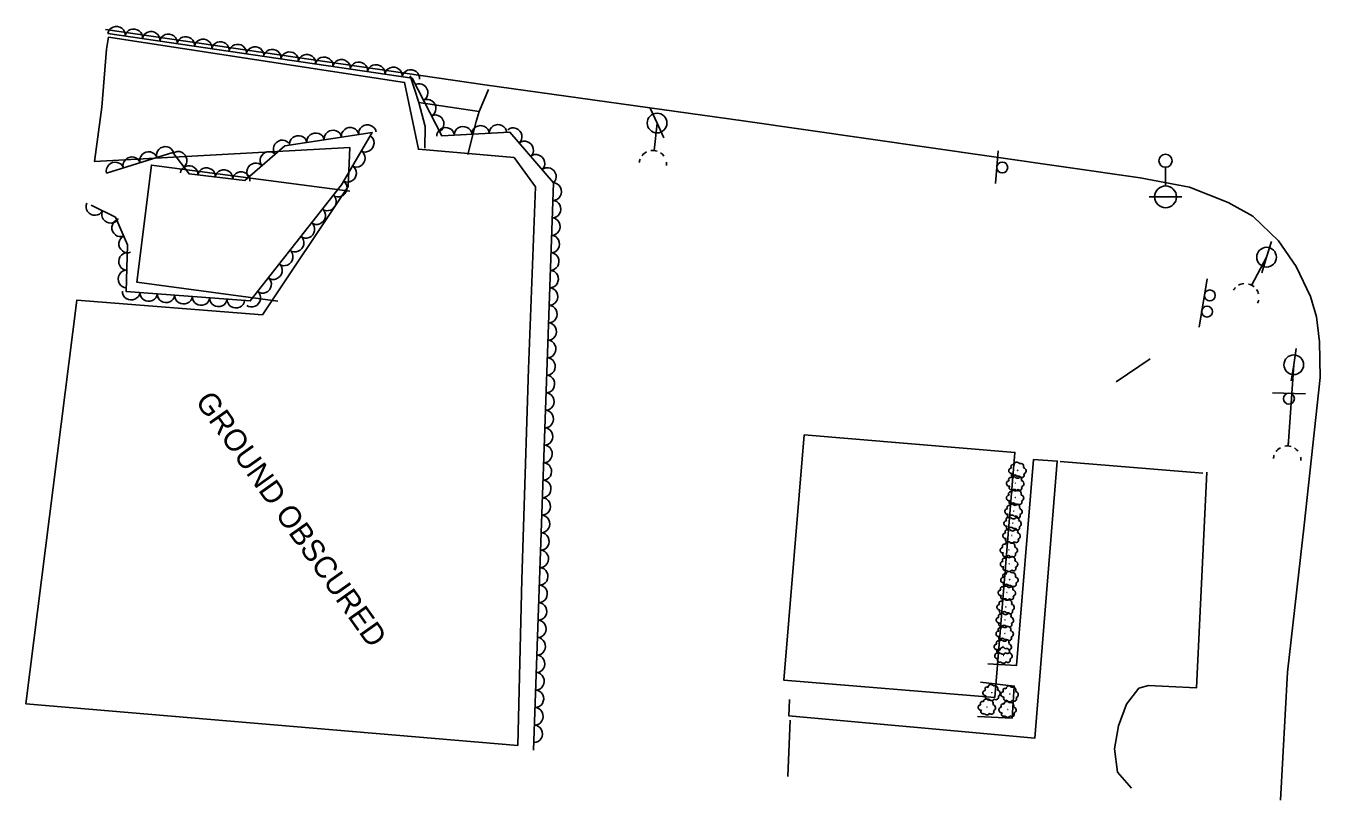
# Model space of a CAD drawing. Extents: x 1746719 to 1766531, y 631721 to 662391.
# Drawn here: x 1763206.3 to 1763502.1, y 632602.3 to 632779.3 of the extents above; entities that cross this region are included whole.
import ezdxf

# ---------------------------------------------------------------- set-up
doc = ezdxf.new("R2010")
doc.units = 0
for name, color, linetype in [('SURVEY - AERIAL SURVEY - Photo Control - Points - Elevations', 7, 'Continuous'), ('SURVEY - AERIAL SURVEY - Photo Control - Points - Locators', 7, 'Continuous'), ('SURVEY - AERIAL SURVEY - Photo Control with Text', 7, 'Continuous'), ('SURVEY - CENTERLINE - Existing Roads - Development', 7, 'Continuous'), ('SURVEY - CENTERLINE - Existing Roads Curve Text', 7, 'Continuous'), ('SURVEY - CONTROL - Grid', 7, 'Continuous')]:
    doc.layers.add(name, color=color, linetype=linetype)

msp = doc.modelspace()

# ---------------------------------------------------------------- linework, layer by layer
at = {"layer": 'SURVEY - AERIAL SURVEY - Photo Control - Points - Elevations'}
for points in [[(1763493.12, 632602.33), (1763494.69, 632631.56), (1763498.49, 632665.21), (1763502.14, 632698.92), (1763501.96, 632707.07), (1763501.3, 632712.82), (1763499.95, 632717.42), (1763496.65, 632724.29), (1763492.64, 632730.17), (1763486.79, 632735.8), (1763481.09, 632738.95), (1763472.31, 632742.44), (1763461, 632744.54), (1763427.02, 632749.42), (1763370.25, 632757.58), (1763311.24, 632765.81), (1763224.55, 632778.43)], [(1763312.07, 632764.79), (1763309.9, 632759.7), (1763296.17, 632761.8), (1763294.2, 632767.91)], [(1763296.17, 632761.8), (1763297.59, 632756.31), (1763297.55, 632751.35)], [(1763307.37, 632749.91), (1763309.25, 632757.41), (1763309.9, 632759.7)], [(1763442.71, 632679.75), (1763475.31, 632677.09)], [(1763459.02, 632605.06), (1763455.81, 632608.71), (1763455.17, 632614.02), (1763456.06, 632619.29), (1763457.86, 632624.3), (1763460.74, 632627.91), (1763462.91, 632628.56), (1763467.57, 632628.29), (1763473.86, 632627.99), (1763476.23, 632677.3)], [(1763381.03, 632620.62), (1763380.48, 632607.72)]]:
    msp.add_lwpolyline(points, dxfattribs=at)
at = {"layer": 'SURVEY - AERIAL SURVEY - Photo Control - Points - Locators'}
msp.add_lwpolyline([(1763225.25, 632776.7), (1763292.89, 632766.36), (1763296.04, 632751.11), (1763317.9, 632749.23), (1763322.81, 632742.51), (1763321.24, 632700.92), (1763319.65, 632652.79), (1763318.76, 632614.83), (1763206.34, 632624.37), (1763217.98, 632716.59), (1763260.38, 632713.26), (1763280.02, 632742.58), (1763280.4, 632751.46), (1763221.99, 632748.32), (1763223.73, 632760.75), (1763224.77, 632773.97), (1763225.25, 632776.7)], dxfattribs=at)
at = {"layer": 'SURVEY - AERIAL SURVEY - Photo Control with Text'}
for points in [[(1763225.06, 632777.56), (1763294.65, 632767.33), (1763301.44, 632754.13), (1763316.96, 632754.99), (1763326.91, 632743.43), (1763322.38, 632613.72)], [(1763224.79, 632745.66), (1763239.92, 632750.35), (1763243.63, 632745.45), (1763256.41, 632743.95), (1763265.52, 632751.84), (1763285.46, 632754.96), (1763278.44, 632742.94), (1763257.61, 632716.44), (1763229.22, 632718.62), (1763229.56, 632729.22), (1763226.79, 632735.58), (1763221.23, 632738.31)]]:
    msp.add_lwpolyline(points, dxfattribs=at)
for centre in [(1763433.02, 632677.71), (1763432.5, 632674.79), (1763432.47, 632671.48), (1763432.12, 632668.38), (1763431.91, 632665.63), (1763431.67, 632662.83), (1763431.04, 632659.53), (1763431.09, 632656.35), (1763431.18, 632652.73), (1763430.59, 632649.8), (1763430.3, 632646.49), (1763430.15, 632643.55), (1763430.1, 632640.42), (1763429.68, 632637.45), (1763429.81, 632635.39), (1763427.11, 632626.89), (1763431.23, 632626.58), (1763426.03, 632623.58), (1763430.75, 632623.03)]:
    msp.add_circle(centre, 0.022, dxfattribs=at)
for centre, radius, start, end in [((1763431.61, 632677.63), 0.629, 89.3771, 282.7968), ((1763431.91, 632678.58), 0.433, 49.3564, 228.1021), ((1763432.07, 632676.66), 0.479, 131.9958, 309.3149), ((1763432.82, 632678.95), 0.631, 27.2403, 184.0292), ((1763433.67, 632678.59), 0.719, 336.293, 113.8172), ((1763434.24, 632677.59), 0.714, 287.1888, 83.0273), ((1763431.09, 632674.71), 0.629, 89.3771, 282.7968), ((1763431.38, 632675.66), 0.433, 49.3564, 228.1021), ((1763431.55, 632673.74), 0.479, 131.9958, 309.3149), ((1763432.3, 632676.03), 0.631, 27.2403, 184.0292), ((1763432.98, 632676.6), 0.679, 207.2828, 334.1285), ((1763433.15, 632675.67), 0.719, 336.293, 113.8172), ((1763433.48, 632673.7), 0.527, 217.4417, 32.442), ((1763434.01, 632676.62), 0.527, 217.4417, 32.442), ((1763433.72, 632674.67), 0.714, 287.1888, 83.0273), ((1763431.06, 632671.4), 0.629, 89.3771, 282.7968), ((1763431.36, 632672.35), 0.433, 49.3564, 228.1021), ((1763432.27, 632672.72), 0.631, 27.2403, 184.0292), ((1763432.46, 632673.68), 0.679, 207.2828, 334.1285), ((1763433.12, 632672.35), 0.719, 336.293, 113.8172), ((1763433.69, 632671.36), 0.714, 287.1888, 83.0273), ((1763430.7, 632668.3), 0.629, 89.3771, 282.7968), ((1763431, 632669.25), 0.433, 49.3564, 228.1021), ((1763431.52, 632670.43), 0.479, 131.9958, 309.3149), ((1763431.91, 632669.63), 0.631, 27.2403, 184.0292), ((1763432.43, 632670.37), 0.679, 207.2828, 334.1285), ((1763432.76, 632669.26), 0.719, 336.293, 113.8172), ((1763433.46, 632670.39), 0.527, 217.4417, 32.442), ((1763433.33, 632668.26), 0.714, 287.1888, 83.0273), ((1763430.49, 632665.55), 0.629, 89.3771, 282.7968), ((1763430.79, 632666.5), 0.433, 49.3564, 228.1021), ((1763431.16, 632667.33), 0.479, 131.9958, 309.3149), ((1763431.7, 632666.87), 0.631, 27.2403, 184.0292), ((1763432.07, 632667.27), 0.679, 207.2828, 334.1285), ((1763432.55, 632666.51), 0.719, 336.293, 113.8172), ((1763433.1, 632667.3), 0.527, 217.4417, 32.442), ((1763433.12, 632665.51), 0.714, 287.1888, 83.0273), ((1763430.26, 632662.75), 0.629, 89.3771, 282.7968), ((1763430.55, 632663.7), 0.433, 49.3564, 228.1021), ((1763430.95, 632664.58), 0.479, 131.9958, 309.3149), ((1763431.46, 632664.07), 0.631, 27.2403, 184.0292), ((1763431.86, 632664.52), 0.679, 207.2828, 334.1285), ((1763432.31, 632663.71), 0.719, 336.293, 113.8172), ((1763432.89, 632664.54), 0.527, 217.4417, 32.442), ((1763432.89, 632662.71), 0.714, 287.1888, 83.0273), ((1763429.63, 632659.45), 0.629, 89.3771, 282.7968), ((1763429.92, 632660.4), 0.433, 49.3564, 228.1021), ((1763430.83, 632660.77), 0.631, 27.2403, 184.0292), ((1763430.72, 632661.78), 0.479, 131.9958, 309.3149), ((1763431.62, 632661.72), 0.679, 207.2828, 334.1285), ((1763431.68, 632660.41), 0.719, 336.293, 113.8172), ((1763432.65, 632661.74), 0.527, 217.4417, 32.442), ((1763432.25, 632659.41), 0.714, 287.1888, 83.0273), ((1763429.68, 632656.27), 0.629, 89.3771, 282.7968), ((1763429.97, 632657.22), 0.433, 49.3564, 228.1021), ((1763430.09, 632658.48), 0.479, 131.9958, 309.3149), ((1763430.89, 632657.59), 0.631, 27.2403, 184.0292), ((1763430.99, 632658.42), 0.679, 207.2828, 334.1285), ((1763431.74, 632657.23), 0.719, 336.293, 113.8172), ((1763432.02, 632658.44), 0.527, 217.4417, 32.442), ((1763432.31, 632656.23), 0.714, 287.1888, 83.0273), ((1763429.77, 632652.65), 0.629, 89.3771, 282.7968), ((1763430.06, 632653.6), 0.433, 49.3564, 228.1021), ((1763430.14, 632655.3), 0.479, 131.9958, 309.3149), ((1763430.97, 632653.98), 0.631, 27.2403, 184.0292), ((1763431.05, 632655.24), 0.679, 207.2828, 334.1285), ((1763431.82, 632653.61), 0.719, 336.293, 113.8172), ((1763432.07, 632655.26), 0.527, 217.4417, 32.442), ((1763432.4, 632652.61), 0.714, 287.1888, 83.0273), ((1763429.18, 632649.72), 0.629, 89.3771, 282.7968), ((1763429.47, 632650.67), 0.433, 49.3564, 228.1021), ((1763430.23, 632651.68), 0.479, 131.9958, 309.3149), ((1763430.38, 632651.04), 0.631, 27.2403, 184.0292), ((1763431.13, 632651.62), 0.679, 207.2828, 334.1285), ((1763431.23, 632650.68), 0.719, 336.293, 113.8172), ((1763432.16, 632651.65), 0.527, 217.4417, 32.442), ((1763431.81, 632649.68), 0.714, 287.1888, 83.0273), ((1763429.19, 632647.36), 0.433, 49.3564, 228.1021), ((1763429.64, 632648.75), 0.479, 131.9958, 309.3149), ((1763430.1, 632647.74), 0.631, 27.2403, 184.0292), ((1763430.54, 632648.69), 0.679, 207.2828, 334.1285), ((1763430.95, 632647.37), 0.719, 336.293, 113.8172), ((1763431.57, 632648.71), 0.527, 217.4417, 32.442), ((1763428.89, 632646.41), 0.629, 89.3771, 282.7968), ((1763429.03, 632644.42), 0.433, 49.3564, 228.1021), ((1763429.35, 632645.44), 0.479, 131.9958, 309.3149), ((1763429.94, 632644.79), 0.631, 27.2403, 184.0292), ((1763430.26, 632645.38), 0.679, 207.2828, 334.1285), ((1763430.79, 632644.43), 0.719, 336.293, 113.8172), ((1763431.28, 632645.41), 0.527, 217.4417, 32.442), ((1763431.52, 632646.37), 0.714, 287.1888, 83.0273), ((1763428.73, 632643.47), 0.629, 89.3771, 282.7968), ((1763428.98, 632641.29), 0.433, 49.3564, 228.1021), ((1763429.19, 632642.5), 0.479, 131.9958, 309.3149), ((1763429.89, 632641.67), 0.631, 27.2403, 184.0292), ((1763430.1, 632642.44), 0.679, 207.2828, 334.1285), ((1763430.74, 632641.3), 0.719, 336.293, 113.8172), ((1763431.13, 632642.46), 0.527, 217.4417, 32.442), ((1763431.36, 632643.43), 0.714, 287.1888, 83.0273), ((1763428.69, 632640.34), 0.629, 89.3771, 282.7968), ((1763428.56, 632638.32), 0.433, 49.3564, 228.1021), ((1763429.15, 632639.37), 0.479, 131.9958, 309.3149), ((1763429.47, 632638.69), 0.631, 27.2403, 184.0292), ((1763430.05, 632639.31), 0.679, 207.2828, 334.1285), ((1763430.32, 632638.32), 0.719, 336.293, 113.8172), ((1763431.08, 632639.34), 0.527, 217.4417, 32.442), ((1763431.32, 632640.3), 0.714, 287.1888, 83.0273), ((1763428.26, 632637.37), 0.629, 89.3771, 282.7968), ((1763428.4, 632635.31), 0.629, 89.3771, 282.7968), ((1763428.72, 632636.4), 0.479, 131.9958, 309.3149), ((1763428.7, 632636.26), 0.433, 49.3564, 228.1021), ((1763429.61, 632636.63), 0.631, 27.2403, 184.0292), ((1763429.63, 632636.34), 0.679, 207.2828, 334.1285), ((1763430.46, 632636.27), 0.719, 336.293, 113.8172), ((1763430.66, 632636.36), 0.527, 217.4417, 32.442), ((1763430.89, 632637.33), 0.714, 287.1888, 83.0273), ((1763431.03, 632635.27), 0.714, 287.1888, 83.0273), ((1763428.86, 632634.34), 0.479, 131.9958, 309.3149), ((1763429.77, 632634.28), 0.679, 207.2828, 334.1285), ((1763430.8, 632634.3), 0.527, 217.4417, 32.442), ((1763425.69, 632626.81), 0.629, 89.3771, 282.7968), ((1763425.99, 632627.76), 0.433, 49.3564, 228.1021), ((1763426.9, 632628.14), 0.631, 27.2403, 184.0292), ((1763427.75, 632627.77), 0.719, 336.293, 113.8172), ((1763428.32, 632626.77), 0.714, 287.1888, 83.0273), ((1763429.81, 632626.5), 0.629, 89.3771, 282.7968), ((1763430.11, 632627.45), 0.433, 49.3564, 228.1021), ((1763431.02, 632627.82), 0.631, 27.2403, 184.0292), ((1763431.87, 632627.46), 0.719, 336.293, 113.8172), ((1763432.44, 632626.46), 0.714, 287.1888, 83.0273), ((1763424.62, 632623.5), 0.629, 89.3771, 282.7968), ((1763424.91, 632624.45), 0.433, 49.3564, 228.1021), ((1763425.82, 632624.82), 0.631, 27.2403, 184.0292), ((1763426.15, 632625.84), 0.479, 131.9958, 309.3149), ((1763426.67, 632624.46), 0.719, 336.293, 113.8172), ((1763427.06, 632625.78), 0.679, 207.2828, 334.1285), ((1763427.24, 632623.46), 0.714, 287.1888, 83.0273), ((1763428.09, 632625.81), 0.527, 217.4417, 32.442), ((1763429.63, 632623.9), 0.433, 49.3564, 228.1021), ((1763430.27, 632625.53), 0.479, 131.9958, 309.3149), ((1763430.54, 632624.28), 0.631, 27.2403, 184.0292), ((1763431.18, 632625.47), 0.679, 207.2828, 334.1285), ((1763431.39, 632623.91), 0.719, 336.293, 113.8172), ((1763432.21, 632625.49), 0.527, 217.4417, 32.442), ((1763425.08, 632622.53), 0.479, 131.9958, 309.3149), ((1763425.98, 632622.47), 0.679, 207.2828, 334.1285), ((1763427.01, 632622.49), 0.527, 217.4417, 32.442), ((1763429.33, 632622.95), 0.629, 89.3771, 282.7968), ((1763429.79, 632621.98), 0.479, 131.9958, 309.3149), ((1763430.7, 632621.92), 0.679, 207.2828, 334.1285), ((1763431.73, 632621.95), 0.527, 217.4417, 32.442), ((1763431.96, 632622.91), 0.714, 287.1888, 83.0273)]:
    msp.add_arc(centre, radius, start, end, dxfattribs=at)
for centre, major_axis in [((1763227.04, 632777.27), (1.98, -0.29)), ((1763231, 632776.69), (1.98, -0.29)), ((1763234.96, 632776.11), (1.98, -0.29)), ((1763238.91, 632775.53), (1.98, -0.29)), ((1763242.87, 632774.94), (1.98, -0.29)), ((1763246.83, 632774.36), (1.98, -0.29)), ((1763250.79, 632773.78), (1.98, -0.29)), ((1763254.74, 632773.2), (1.98, -0.29)), ((1763258.7, 632772.62), (1.98, -0.29)), ((1763262.66, 632772.04), (1.98, -0.29)), ((1763266.62, 632771.46), (1.98, -0.29)), ((1763270.57, 632770.87), (1.98, -0.29)), ((1763274.53, 632770.29), (1.98, -0.29)), ((1763278.49, 632769.71), (1.98, -0.29)), ((1763282.45, 632769.13), (1.98, -0.29)), ((1763286.4, 632768.55), (1.98, -0.29)), ((1763290.36, 632767.97), (1.98, -0.29)), ((1763294.32, 632767.38), (1.98, -0.29)), ((1763296.33, 632764.08), (0.91, -1.78)), ((1763298.16, 632760.52), (0.91, -1.78)), ((1763284.39, 632754.79), (1.98, 0.31)), ((1763299.99, 632756.96), (0.91, -1.78)), ((1763268.58, 632752.32), (1.98, 0.31)), ((1763272.53, 632752.93), (1.98, 0.31)), ((1763276.49, 632753.55), (1.98, 0.31)), ((1763280.44, 632754.17), (1.98, 0.31)), ((1763283.99, 632752.44), (-1.01, -1.73)), ((1763302.25, 632754.17), (2, 0.11)), ((1763306.25, 632754.4), (2, 0.11)), ((1763310.24, 632754.62), (2, 0.11)), ((1763314.24, 632754.84), (2, 0.11)), ((1763317.79, 632754.03), (1.3, -1.52)), ((1763238.16, 632749.81), (1.91, 0.59)), ((1763264.84, 632751.25), (1.51, 1.31)), ((1763320.4, 632751), (1.3, -1.52)), ((1763226.7, 632746.25), (1.91, 0.59)), ((1763230.52, 632747.44), (1.91, 0.59)), ((1763234.34, 632748.62), (1.91, 0.59)), ((1763241.22, 632748.63), (1.21, -1.59)), ((1763258.79, 632746.01), (1.51, 1.31)), ((1763261.81, 632748.63), (1.51, 1.31)), ((1763281.97, 632748.98), (-1.01, -1.73)), ((1763323.01, 632747.96), (1.3, -1.52)), ((1763243.64, 632745.45), (1.99, -0.23)), ((1763247.62, 632744.98), (1.99, -0.23)), ((1763251.59, 632744.52), (1.99, -0.23)), ((1763255.56, 632744.05), (1.99, -0.23)), ((1763279.95, 632745.53), (-1.01, -1.73)), ((1763325.62, 632744.93), (1.3, -1.52)), ((1763277.82, 632742.15), (-1.24, -1.57)), ((1763326.84, 632741.41), (-0.07, -2)), ((1763275.35, 632739), (-1.24, -1.57)), ((1763326.7, 632737.42), (-0.07, -2)), ((1763222.05, 632737.9), (-1.8, 0.88)), ((1763225.64, 632736.14), (-1.8, 0.88)), ((1763272.88, 632735.86), (-1.24, -1.57)), ((1763227.88, 632733.09), (-0.8, 1.83)), ((1763270.41, 632732.71), (-1.24, -1.57)), ((1763326.56, 632733.42), (-0.07, -2)), ((1763229.48, 632729.42), (-0.8, 1.83)), ((1763267.94, 632729.57), (-1.24, -1.57)), ((1763326.42, 632729.42), (-0.07, -2)), ((1763229.44, 632725.44), (0.06, 2)), ((1763265.46, 632726.43), (-1.24, -1.57)), ((1763326.29, 632725.42), (-0.07, -2)), ((1763262.99, 632723.28), (-1.24, -1.57)), ((1763229.31, 632721.44), (0.06, 2)), ((1763260.52, 632720.14), (-1.24, -1.57)), ((1763326.15, 632721.43), (-0.07, -2)), ((1763230.4, 632718.53), (-1.99, 0.15)), ((1763234.39, 632718.22), (-1.99, 0.15)), ((1763258.05, 632716.99), (-1.24, -1.57)), ((1763326.01, 632717.43), (-0.07, -2)), ((1763238.37, 632717.92), (-1.99, 0.15)), ((1763242.36, 632717.61), (-1.99, 0.15)), ((1763246.35, 632717.3), (-1.99, 0.15)), ((1763250.34, 632717), (-1.99, 0.15)), ((1763254.33, 632716.69), (-1.99, 0.15)), ((1763325.87, 632713.43), (-0.07, -2)), ((1763325.73, 632709.43), (-0.07, -2)), ((1763325.59, 632705.44), (-0.07, -2)), ((1763325.45, 632701.44), (-0.07, -2)), ((1763325.31, 632697.44), (-0.07, -2)), ((1763325.17, 632693.44), (-0.07, -2)), ((1763325.03, 632689.45), (-0.07, -2)), ((1763324.89, 632685.45), (-0.07, -2)), ((1763324.75, 632681.45), (-0.07, -2)), ((1763324.61, 632677.45), (-0.07, -2)), ((1763324.47, 632673.46), (-0.07, -2)), ((1763324.33, 632669.46), (-0.07, -2)), ((1763324.19, 632665.46), (-0.07, -2)), ((1763324.05, 632661.46), (-0.07, -2)), ((1763323.91, 632657.47), (-0.07, -2)), ((1763323.77, 632653.47), (-0.07, -2)), ((1763323.63, 632649.47), (-0.07, -2)), ((1763323.49, 632645.47), (-0.07, -2)), ((1763323.35, 632641.48), (-0.07, -2)), ((1763323.21, 632637.48), (-0.07, -2)), ((1763323.07, 632633.48), (-0.07, -2)), ((1763322.93, 632629.48), (-0.07, -2)), ((1763322.8, 632625.49), (-0.07, -2)), ((1763322.66, 632621.49), (-0.07, -2)), ((1763322.52, 632617.49), (-0.07, -2))]:
    msp.add_ellipse(centre, major_axis=major_axis, ratio=0.940188, start_param=0, end_param=3.141593, dxfattribs=at)
at = {"layer": 'SURVEY - CENTERLINE - Existing Roads - Development'}
for p, q in [((1763350.59, 632757.09), (1763349.02, 632760.5)), ((1763350.59, 632757.09), (1763349.93, 632750.78)), ((1763350.59, 632757.09), (1763352.16, 632753.68)), ((1763350, 632751.47), (1763349.93, 632750.78)), ((1763466.81, 632746.97), (1763466.82, 632742.72)), ((1763466.82, 632740.22), (1763463.07, 632740.21)), ((1763466.82, 632740.22), (1763470.57, 632740.23)), ((1763489.89, 632726.43), (1763490.99, 632730.01)), ((1763489.89, 632726.43), (1763486.46, 632719.99)), ((1763489.89, 632726.43), (1763488.79, 632722.84)), ((1763486.77, 632720.59), (1763486.46, 632719.99)), ((1763496.11, 632701.83), (1763496.7, 632705.54)), ((1763496.11, 632701.83), (1763494.8, 632683.26)), ((1763496.11, 632701.83), (1763495.53, 632698.13)), ((1763494.84, 632683.96), (1763494.8, 632683.26))]:
    msp.add_line(p, q, dxfattribs=at)
for centre, radius in [((1763350.59, 632757.09), 2.25), ((1763466.81, 632748.47), 1.5), ((1763466.82, 632740.22), 2.5), ((1763489.89, 632726.43), 2.25), ((1763496.11, 632701.83), 2.25)]:
    msp.add_circle(centre, radius, dxfattribs=at)
for centre, major_axis, ratio, start_param, end_param in [((1763349.63, 632747.7), (3.11, -0.33), 0.997989, 2.883049, 3.125465), ((1763349.63, 632747.7), (3.11, -0.33), 0.997989, 2.156577, 2.588895), ((1763349.63, 632747.7), (3.11, -0.33), 0.997989, 1.352995, 1.815775), ((1763349.63, 632747.7), (3.11, -0.33), 0.997989, 0.730907, 1.085951), ((1763349.63, 632747.7), (3.11, -0.33), 0.997989, 0, 0.255182), ((1763485.08, 632717.37), (2.76, -1.47), 0.956516, 2.883049, 3.125465), ((1763485.08, 632717.37), (2.76, -1.47), 0.956516, 2.156577, 2.588895), ((1763485.08, 632717.37), (2.76, -1.47), 0.956516, 1.352995, 1.815775), ((1763485.08, 632717.37), (2.76, -1.47), 0.956516, 0.730907, 1.085951), ((1763485.08, 632717.37), (2.76, -1.47), 0.956516, 0, 0.255182), ((1763494.6, 632680.16), (3.12, -0.22), 0.999751, 2.156577, 2.588895), ((1763494.6, 632680.16), (3.12, -0.22), 0.999751, 1.352995, 1.815775), ((1763494.6, 632680.16), (3.12, -0.22), 0.999751, 2.883049, 3.125465), ((1763494.6, 632680.16), (3.12, -0.22), 0.999751, 0.730907, 1.085951), ((1763494.6, 632680.16), (3.12, -0.22), 0.999751, 0, 0.255182)]:
    msp.add_ellipse(centre, major_axis=major_axis, ratio=ratio, start_param=start_param, end_param=end_param, dxfattribs=at)
at = {"layer": 'SURVEY - CENTERLINE - Existing Roads Curve Text'}
for points in [[(1763263.89, 632716.41), (1763231.7, 632720.71), (1763235.01, 632747.46), (1763280.38, 632741.49)], [(1763426.23, 632633.51), (1763432.76, 632633.12), (1763436.65, 632680.17), (1763442.06, 632679.84), (1763436.97, 632616.51), (1763380.68, 632621.6), (1763380.83, 632625.32)], [(1763423.82, 632621.45), (1763431.75, 632621.04), (1763432.22, 632628.4), (1763424.48, 632629.28)]]:
    msp.add_lwpolyline(points, dxfattribs=at)
msp.add_lwpolyline([(1763427.76, 632625.76), (1763379.6, 632629.74), (1763384.24, 632685.79), (1763432.4, 632681.8)], close=True, dxfattribs=at)
at = {"layer": 'SURVEY - CONTROL - Grid'}
for p, q in [((1763427.98, 632743.26), (1763428.52, 632750.74)), ((1763474.46, 632710.43), (1763476.33, 632721.48)), ((1763491.27, 632695.44), (1763498.76, 632695.2))]:
    msp.add_line(p, q, dxfattribs=at)
msp.add_lwpolyline([(1763463.33, 632703.21), (1763455.5, 632697.9)], dxfattribs=at)
msp.add_lwpolyline([(1763463.33, 632703.21), (1763455.5, 632697.9)], dxfattribs=at)
for centre in [(1763429.48, 632746.93), (1763476.93, 632717.69), (1763476.31, 632714), (1763495, 632694.09)]:
    msp.add_circle(centre, 1.25, dxfattribs=at)

# ---------------------------------------------------------------- texts
at = {"layer": 'SURVEY - AERIAL SURVEY - Photo Control - Points - Locators'}
msp.add_text('GROUND OBSCURED', height=5, rotation=305.3359, dxfattribs=at).set_placement((1763244.9, 632693.48))

doc.saveas('drawing.dxf')
